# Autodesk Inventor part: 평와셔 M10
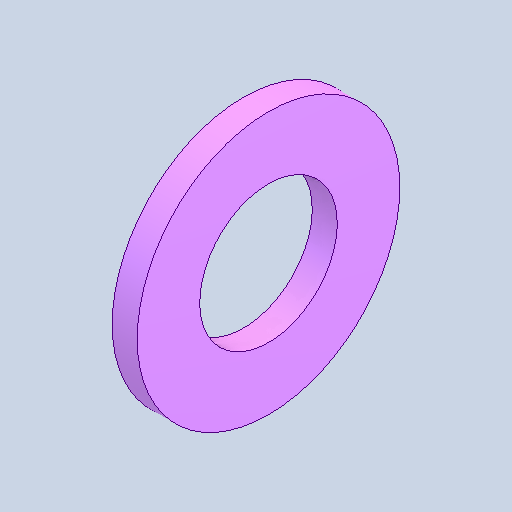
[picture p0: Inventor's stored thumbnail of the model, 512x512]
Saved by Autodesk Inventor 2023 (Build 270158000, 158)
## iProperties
Created: 2024-09
Part Number: 평와셔 M10
Material: 강철, 연강
Description: 평면 와셔
Document SubType Name: Modeling
Designer: asung
Density: 7.85 g/cm^3
Appearance: 기본값
Author: jhkim
Sending System: Autodesk Inventor 2025
Preprocessor: ST-DEVELOPER v20
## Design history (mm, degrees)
feature "Solid1"
node "솔리드1"
